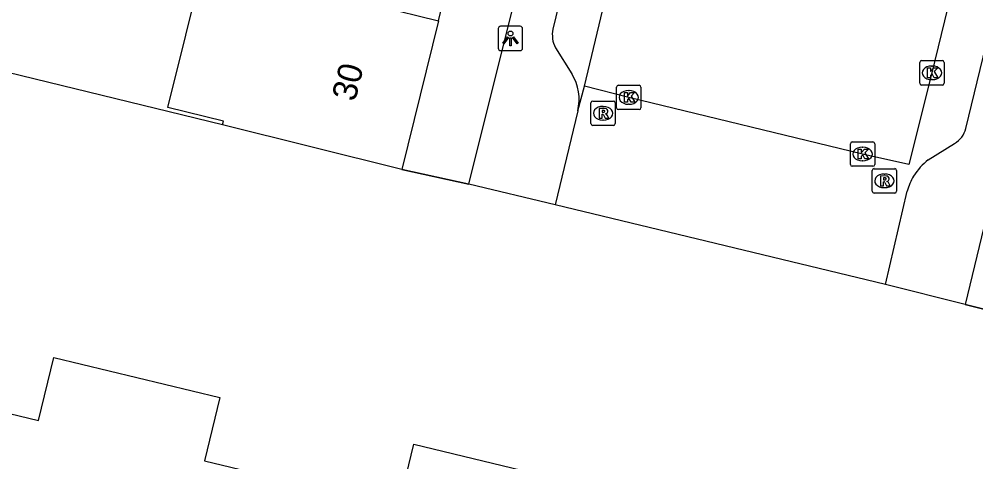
# Model space of a CAD drawing. Extents: x 162812 to 163818, y 381639 to 382470.
# Drawn here: x 163102.96 to 163142.25, y 382204.88 to 382223.04 of the extents above; entities that cross this region are included whole.
import ezdxf

# ---------------------------------------------------------------- set-up
doc = ezdxf.new("R2010")
doc.units = 0
for name, color, linetype in [('IMGEO_Erf', 7, 'Continuous'), ('IMGEO_Hek', 7, 'Continuous'), ('IMGEO_Kolk', 7, 'Continuous'), ('IMGEO_Lichtpunt', 7, 'Continuous'), ('IMGEO_Pand', 7, 'Continuous'), ('IMGEO_Pand_nummerreeks', 7, 'Continuous'), ('IMGEO_Parkeervlak_open', 7, 'Continuous'), ('IMGEO_Rijbaan_lokaal_open', 7, 'Continuous'), ('IMGEO_Rioolput', 7, 'Continuous'), ('IMGEO_Voetpad_open', 7, 'Continuous')]:
    doc.layers.add(name, color=color, linetype=linetype)

msp = doc.modelspace()

# ---------------------------------------------------------------- linework, layer by layer
at = {"layer": 'IMGEO_Erf'}
for points in [[(163111.314, 382218.702), (163093.672, 382223)], [(163121.429, 382216.275), (163118.671, 382216.877)], [(163141.809, 382211.34), (163144.013, 382210.786)]]:
    msp.add_lwpolyline(points, dxfattribs=at)
at = {"layer": 'IMGEO_Hek'}
for points in [[(163118.671, 382216.877), (163121.429, 382216.275)], [(163144.013, 382210.786), (163141.809, 382211.34)]]:
    msp.add_lwpolyline(points, dxfattribs=at)
at = {"layer": 'IMGEO_Kolk'}
for p, q in [((163139.943, 382220.415), (163139.943, 382221.267)), ((163140.018, 382221.341), (163140.87, 382221.341)), ((163140.431, 382221.121), (163140.456, 382221.121)), ((163140.944, 382221.267), (163140.944, 382220.415)), ((163127.495, 382219.405), (163127.495, 382220.257)), ((163127.57, 382220.331), (163128.422, 382220.331)), ((163128.496, 382220.257), (163128.496, 382219.405)), ((163140.87, 382220.341), (163140.018, 382220.341)), ((163140.454, 382220.561), (163140.429, 382220.561)), ((163127.983, 382220.111), (163128.008, 382220.111)), ((163128.006, 382219.551), (163127.981, 382219.551)), ((163128.422, 382219.331), (163127.57, 382219.331)), ((163137.094, 382217.081), (163137.094, 382217.933)), ((163137.169, 382218.007), (163138.021, 382218.007)), ((163138.095, 382217.933), (163138.095, 382217.081)), ((163137.582, 382217.787), (163137.607, 382217.787)), ((163137.605, 382217.227), (163137.58, 382217.227)), ((163138.021, 382217.007), (163137.169, 382217.007))]:
    msp.add_line(p, q, dxfattribs=at)
for points in [[(163139.943, 382220.415), (163139.943, 382221.267)], [(163140.018, 382221.341), (163140.87, 382221.341)], [(163140.264, 382221.041), (163140.387, 382221.041), (163140.387, 382220.89), (163140.517, 382221.041), (163140.681, 382221.041), (163140.535, 382220.89), (163140.688, 382220.641), (163140.536, 382220.641), (163140.451, 382220.805), (163140.387, 382220.738), (163140.387, 382220.641), (163140.264, 382220.641), (163140.264, 382221.041)], [(163140.944, 382221.267), (163140.944, 382220.415)], [(163127.495, 382219.405), (163127.495, 382220.257)], [(163127.57, 382220.331), (163128.422, 382220.331)], [(163128.496, 382220.257), (163128.496, 382219.405)], [(163140.87, 382220.341), (163140.018, 382220.341)], [(163127.816, 382220.031), (163127.939, 382220.031), (163127.939, 382219.88), (163128.069, 382220.031), (163128.233, 382220.031), (163128.087, 382219.88), (163128.24, 382219.631), (163128.088, 382219.631), (163128.003, 382219.795), (163127.939, 382219.728), (163127.939, 382219.631), (163127.816, 382219.631), (163127.816, 382220.031)], [(163128.422, 382219.331), (163127.57, 382219.331)], [(163137.094, 382217.081), (163137.094, 382217.933)], [(163137.169, 382218.007), (163138.021, 382218.007)], [(163138.095, 382217.933), (163138.095, 382217.081)], [(163137.415, 382217.707), (163137.538, 382217.707), (163137.538, 382217.556), (163137.668, 382217.707), (163137.832, 382217.707), (163137.686, 382217.556), (163137.839, 382217.307), (163137.687, 382217.307), (163137.602, 382217.471), (163137.538, 382217.404), (163137.538, 382217.307), (163137.415, 382217.307), (163137.415, 382217.707)], [(163138.021, 382217.007), (163137.169, 382217.007)]]:
    msp.add_lwpolyline(points, dxfattribs=at)
for centre, start, end in [((163140.02, 382221.265), 91.552, 178.448), ((163140.02, 382221.265), 91.552, 178.448), ((163140.868, 382221.265), 1.552, 88.448), ((163140.868, 382221.265), 1.552, 88.448), ((163127.572, 382220.255), 91.552, 178.448), ((163127.572, 382220.255), 91.552, 178.448), ((163128.42, 382220.255), 1.552, 88.448), ((163128.42, 382220.255), 1.552, 88.448), ((163140.02, 382220.417), 181.552, 268.448), ((163140.02, 382220.417), 181.552, 268.448), ((163140.868, 382220.417), 271.552, 358.448), ((163140.868, 382220.417), 271.552, 358.448), ((163127.572, 382219.407), 181.552, 268.448), ((163127.572, 382219.407), 181.552, 268.448), ((163128.42, 382219.407), 271.552, 358.448), ((163128.42, 382219.407), 271.552, 358.448), ((163137.171, 382217.931), 91.552, 178.448), ((163137.171, 382217.931), 91.552, 178.448), ((163138.019, 382217.931), 1.552, 88.448), ((163138.019, 382217.931), 1.552, 88.448), ((163137.171, 382217.083), 181.552, 268.448), ((163137.171, 382217.083), 181.552, 268.448), ((163138.019, 382217.083), 271.552, 358.448), ((163138.019, 382217.083), 271.552, 358.448)]:
    msp.add_arc(centre, 0.0765, start, end, dxfattribs=at)
for centre, major_axis, ratio, start_param, end_param in [((163140.43, 382220.841), (-0.387, 0.002), 0.722429, 4.712389, 7.853982), ((163140.455, 382220.841), (-0.39, 0.002), 0.717154, 1.570796, 4.712389), ((163127.982, 382219.831), (-0.387, 0.002), 0.722429, 4.712389, 7.853982), ((163128.007, 382219.831), (-0.39, 0.002), 0.717154, 1.570796, 4.712389), ((163137.581, 382217.507), (-0.387, 0.002), 0.722429, 4.712389, 7.853982), ((163137.606, 382217.507), (-0.39, 0.002), 0.717154, 1.570796, 4.712389)]:
    msp.add_ellipse(centre, major_axis=major_axis, ratio=ratio, start_param=start_param, end_param=end_param, dxfattribs=at)
at = {"layer": 'IMGEO_Lichtpunt'}
for p, q in [((163122.639, 382222.655), (163122.639, 382221.848)), ((163122.639, 382222.655), (163122.639, 382221.848)), ((163123.541, 382222.75), (163122.733, 382222.75)), ((163123.541, 382222.75), (163122.733, 382222.75)), ((163123.635, 382221.848), (163123.635, 382222.655)), ((163123.635, 382221.848), (163123.635, 382222.655)), ((163122.733, 382221.754), (163123.541, 382221.754)), ((163122.733, 382221.754), (163123.541, 382221.754))]:
    msp.add_line(p, q, dxfattribs=at)
for points in [[(163123.013, 382222.319), (163123.052, 382222.291), (163122.864, 382222.029), (163122.826, 382222.056), (163123.013, 382222.319)], [(163123.115, 382222.271), (163123.162, 382222.271), (163123.162, 382221.949), (163123.115, 382221.949), (163123.115, 382222.271)], [(163123.225, 382222.291), (163123.263, 382222.318), (163123.45, 382222.056), (163123.411, 382222.028), (163123.225, 382222.291)]]:
    msp.add_lwpolyline(points, dxfattribs=at)
msp.add_circle((163123.138, 382222.453), 0.0994, dxfattribs=at)
for centre, start, end in [((163122.733, 382222.655), 90, 180), ((163122.733, 382222.655), 90, 180), ((163123.541, 382222.655), 0, 90), ((163123.541, 382222.655), 0, 90), ((163122.733, 382221.848), 180, 270), ((163122.733, 382221.848), 180, 270), ((163123.541, 382221.848), 270, 0), ((163123.541, 382221.848), 270, 360)]:
    msp.add_arc(centre, 0.0946, start, end, dxfattribs=at)
at = {"layer": 'IMGEO_Pand'}
for points in [[(163120.183, 382222.974), (163121.633, 382228.819)], [(163111.314, 382218.702), (163111.353, 382218.859), (163109.073, 382219.425), (163110.546, 382225.365), (163112.826, 382224.799)], [(163112.826, 382224.799), (163120.183, 382222.974)], [(163120.183, 382222.974), (163118.671, 382216.877)], [(163118.671, 382216.877), (163111.314, 382218.702)], [(163083.017, 382200.67), (163084.847, 382208.279), (163088.88, 382207.309), (163090.13, 382212.51), (163096.915, 382210.878), (163096.312, 382208.371), (163103.765, 382206.579), (163104.386, 382209.159), (163111.204, 382207.519), (163110.58, 382204.923), (163118.542, 382203.008), (163119.164, 382205.595), (163126.021, 382203.946)]]:
    msp.add_lwpolyline(points, dxfattribs=at)
at = {"layer": 'IMGEO_Parkeervlak_open'}
for points in [[(163125.897, 382219.282), (163126.177, 382220.3)], [(163138.535, 382212.15), (163124.973, 382215.424)]]:
    msp.add_lwpolyline(points, dxfattribs=at)
at = {"layer": 'IMGEO_Rijbaan_lokaal_open'}
for points in [[(163126.177, 382220.3), (163127.154, 382224.374), (163131.05, 382240.49), (163132.188, 382245.406)], [(163145.726, 382242.413), (163144.32, 382236.804), (163140.443, 382220.841), (163139.498, 382217.076), (163137.595, 382217.507), (163127.997, 382219.832), (163126.177, 382220.3)]]:
    msp.add_lwpolyline(points, dxfattribs=at)
at = {"layer": 'IMGEO_Rioolput'}
for p, q in [((163126.441, 382218.757), (163126.441, 382219.609)), ((163126.516, 382219.683), (163127.368, 382219.683)), ((163127.442, 382219.609), (163127.442, 382218.757)), ((163126.929, 382219.463), (163126.954, 382219.463)), ((163127.368, 382218.683), (163126.516, 382218.683)), ((163126.952, 382218.903), (163126.927, 382218.903)), ((163137.992, 382215.982), (163137.992, 382216.834)), ((163138.067, 382216.908), (163138.919, 382216.908)), ((163138.993, 382216.834), (163138.993, 382215.982)), ((163138.48, 382216.688), (163138.505, 382216.688)), ((163138.503, 382216.128), (163138.478, 382216.128)), ((163138.919, 382215.908), (163138.067, 382215.908))]:
    msp.add_line(p, q, dxfattribs=at)
for points in [[(163126.441, 382218.757), (163126.441, 382219.609)], [(163126.516, 382219.683), (163127.368, 382219.683)], [(163127.442, 382219.609), (163127.442, 382218.757)], [(163127.03, 382219.381), (163126.778, 382219.383), (163126.778, 382218.983)], [(163126.778, 382218.983), (163126.902, 382218.983), (163126.902, 382219.145), (163126.913, 382219.145)], [(163126.956, 382219.302), (163126.902, 382219.302), (163126.902, 382219.221)], [(163126.902, 382219.221), (163126.954, 382219.221)], [(163126.96, 382219.116), (163127.031, 382218.983), (163127.171, 382218.983), (163127.106, 382219.109)], [(163127.368, 382218.683), (163126.516, 382218.683)], [(163137.992, 382215.982), (163137.992, 382216.834)], [(163138.067, 382216.908), (163138.919, 382216.908)], [(163138.993, 382216.834), (163138.993, 382215.982)], [(163138.581, 382216.606), (163138.329, 382216.608), (163138.329, 382216.208)], [(163138.329, 382216.208), (163138.453, 382216.208), (163138.453, 382216.37), (163138.464, 382216.37)], [(163138.507, 382216.527), (163138.453, 382216.527), (163138.453, 382216.446)], [(163138.453, 382216.446), (163138.505, 382216.446)], [(163138.511, 382216.341), (163138.582, 382216.208), (163138.722, 382216.208), (163138.657, 382216.334)], [(163138.919, 382215.908), (163138.067, 382215.908)]]:
    msp.add_lwpolyline(points, dxfattribs=at)
for centre, radius, start, end in [((163126.518, 382219.607), 0.0765, 91.552, 178.448), ((163126.518, 382219.607), 0.0765, 91.552, 178.448), ((163127.366, 382219.607), 0.0765, 1.552, 88.448), ((163127.366, 382219.607), 0.0765, 1.552, 88.448), ((163126.912, 382219.092), 0.0533, 26.0293, 88.6989), ((163126.938, 382219.41), 0.19, 274.7715, 282.9687), ((163126.962, 382219.206), 0.0964, 77.0061, 93.1865), ((163126.976, 382219.263), 0.0378, 276.6634, 79.6772), ((163127.029, 382219.271), 0.109, 350.3612, 89.416), ((163127.027, 382219.271), 0.112, 277.5842, 350.9817), ((163127.011, 382219.056), 0.108, 29.5134, 73.7905), ((163126.518, 382218.759), 0.0765, 181.552, 268.448), ((163126.518, 382218.759), 0.0765, 181.552, 268.448), ((163127.366, 382218.759), 0.0765, 271.552, 358.448), ((163127.366, 382218.759), 0.0765, 271.552, 358.448), ((163138.069, 382216.832), 0.0765, 91.552, 178.448), ((163138.069, 382216.832), 0.0765, 91.552, 178.448), ((163138.917, 382216.832), 0.0765, 1.552, 88.448), ((163138.917, 382216.832), 0.0765, 1.552, 88.448), ((163138.463, 382216.317), 0.0533, 26.0293, 88.6989), ((163138.489, 382216.635), 0.19, 274.7715, 282.9687), ((163138.513, 382216.431), 0.0964, 77.0061, 93.1865), ((163138.527, 382216.488), 0.0378, 276.6634, 79.6772), ((163138.58, 382216.496), 0.109, 350.3612, 89.416), ((163138.578, 382216.496), 0.112, 277.5842, 350.9817), ((163138.562, 382216.281), 0.108, 29.5134, 73.7905), ((163138.069, 382215.984), 0.0765, 181.552, 268.448), ((163138.069, 382215.984), 0.0765, 181.552, 268.448), ((163138.917, 382215.984), 0.0765, 271.552, 358.448), ((163138.917, 382215.984), 0.0765, 271.552, 358.448)]:
    msp.add_arc(centre, radius, start, end, dxfattribs=at)
for centre, major_axis, ratio, start_param, end_param in [((163126.928, 382219.183), (-0.387, 0.002), 0.722429, 4.712389, 7.853982), ((163126.953, 382219.183), (-0.39, 0.002), 0.717154, 1.570796, 4.712389), ((163138.479, 382216.408), (-0.387, 0.002), 0.722429, 4.712389, 7.853982), ((163138.504, 382216.408), (-0.39, 0.002), 0.717154, 1.570796, 4.712389)]:
    msp.add_ellipse(centre, major_axis=major_axis, ratio=ratio, start_param=start_param, end_param=end_param, dxfattribs=at)
at = {"layer": 'IMGEO_Voetpad_open'}
for points in [[(163121.429, 382216.275), (163128.151, 382243.17)], [(163129.89, 382243.252), (163124.878, 382222.632)], [(163147.445, 382243.263), (163147.088, 382241.552), (163147.902, 382239.162), (163148.048, 382237.184), (163141.809, 382211.34)], [(163141.833, 382218.56), (163146.791, 382238.957)], [(163124.984, 382221.872), (163125.654, 382220.8)], [(163125.897, 382219.282), (163124.973, 382215.424)], [(163140.293, 382217.27), (163141.371, 382217.94)], [(163124.973, 382215.424), (163121.429, 382216.275)], [(163138.535, 382212.15), (163139.43, 382215.984)], [(163141.809, 382211.34), (163138.535, 382212.15)]]:
    msp.add_lwpolyline(points, dxfattribs=at)
for centre, radius, start, end in [((163126.009, 382222.402), 1.154, 168.5294, 207.3507), ((163123.987, 382219.755), 1.968, 346.0997, 32.0897), ((163140.871, 382218.795), 0.99, 300.3235, 346.2924), ((163141.707, 382215.386), 2.355, 126.891, 148.955), ((163141.661, 382215.41), 2.304, 148.8786, 165.5787)]:
    msp.add_arc(centre, radius, start, end, dxfattribs=at)

# ---------------------------------------------------------------- texts
at = {"layer": 'IMGEO_Pand_nummerreeks'}
msp.add_text('30', height=1, rotation=76.0681, dxfattribs=at).set_placement((163116.758, 382219.633))

doc.saveas('drawing.dxf')
